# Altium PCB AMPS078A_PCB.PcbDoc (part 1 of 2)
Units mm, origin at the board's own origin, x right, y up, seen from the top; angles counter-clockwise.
Board outline 85 x 120 mm, 4 copper layers (Top Layer, Signal Layer 1, Signal Layer 2, Bottom Layer), stack 1.567 mm thick; 105 components, 52 nets, 354 pads, 440 vias.
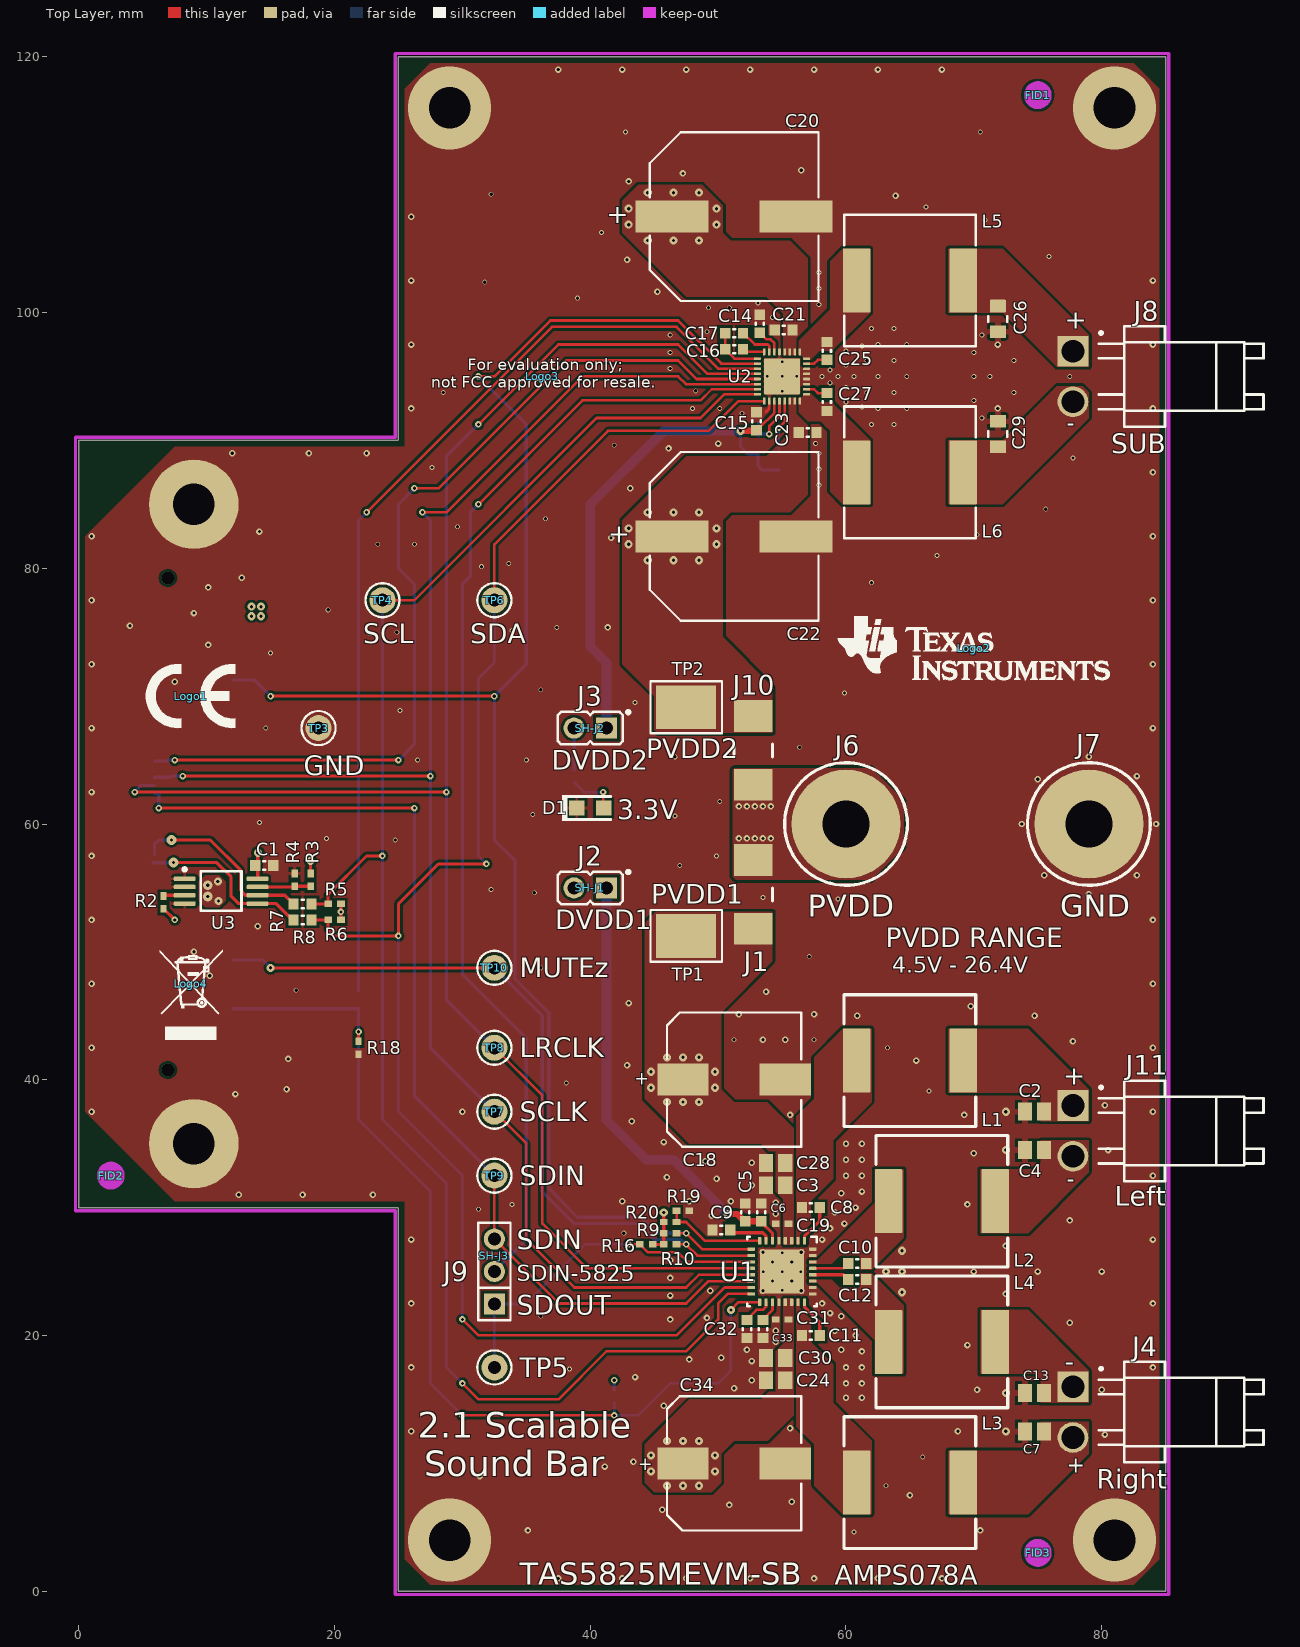
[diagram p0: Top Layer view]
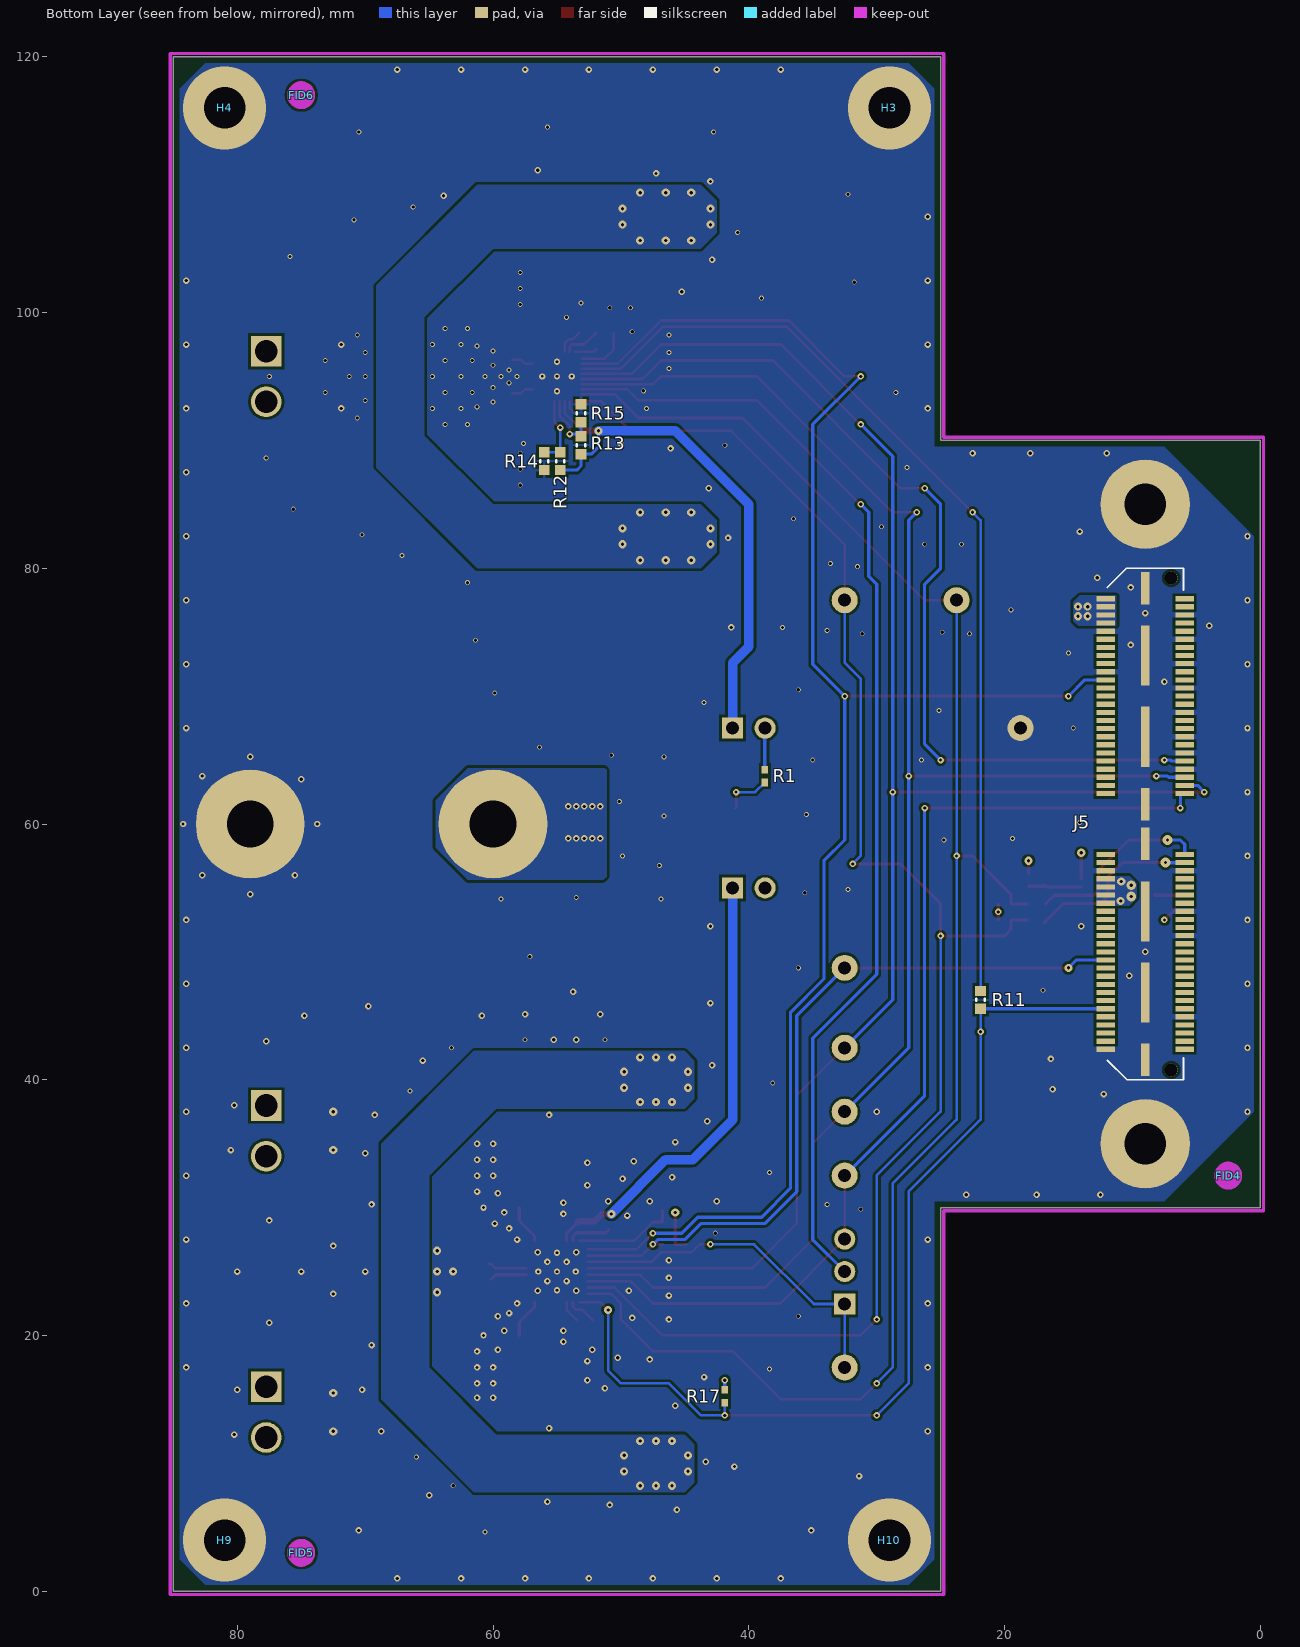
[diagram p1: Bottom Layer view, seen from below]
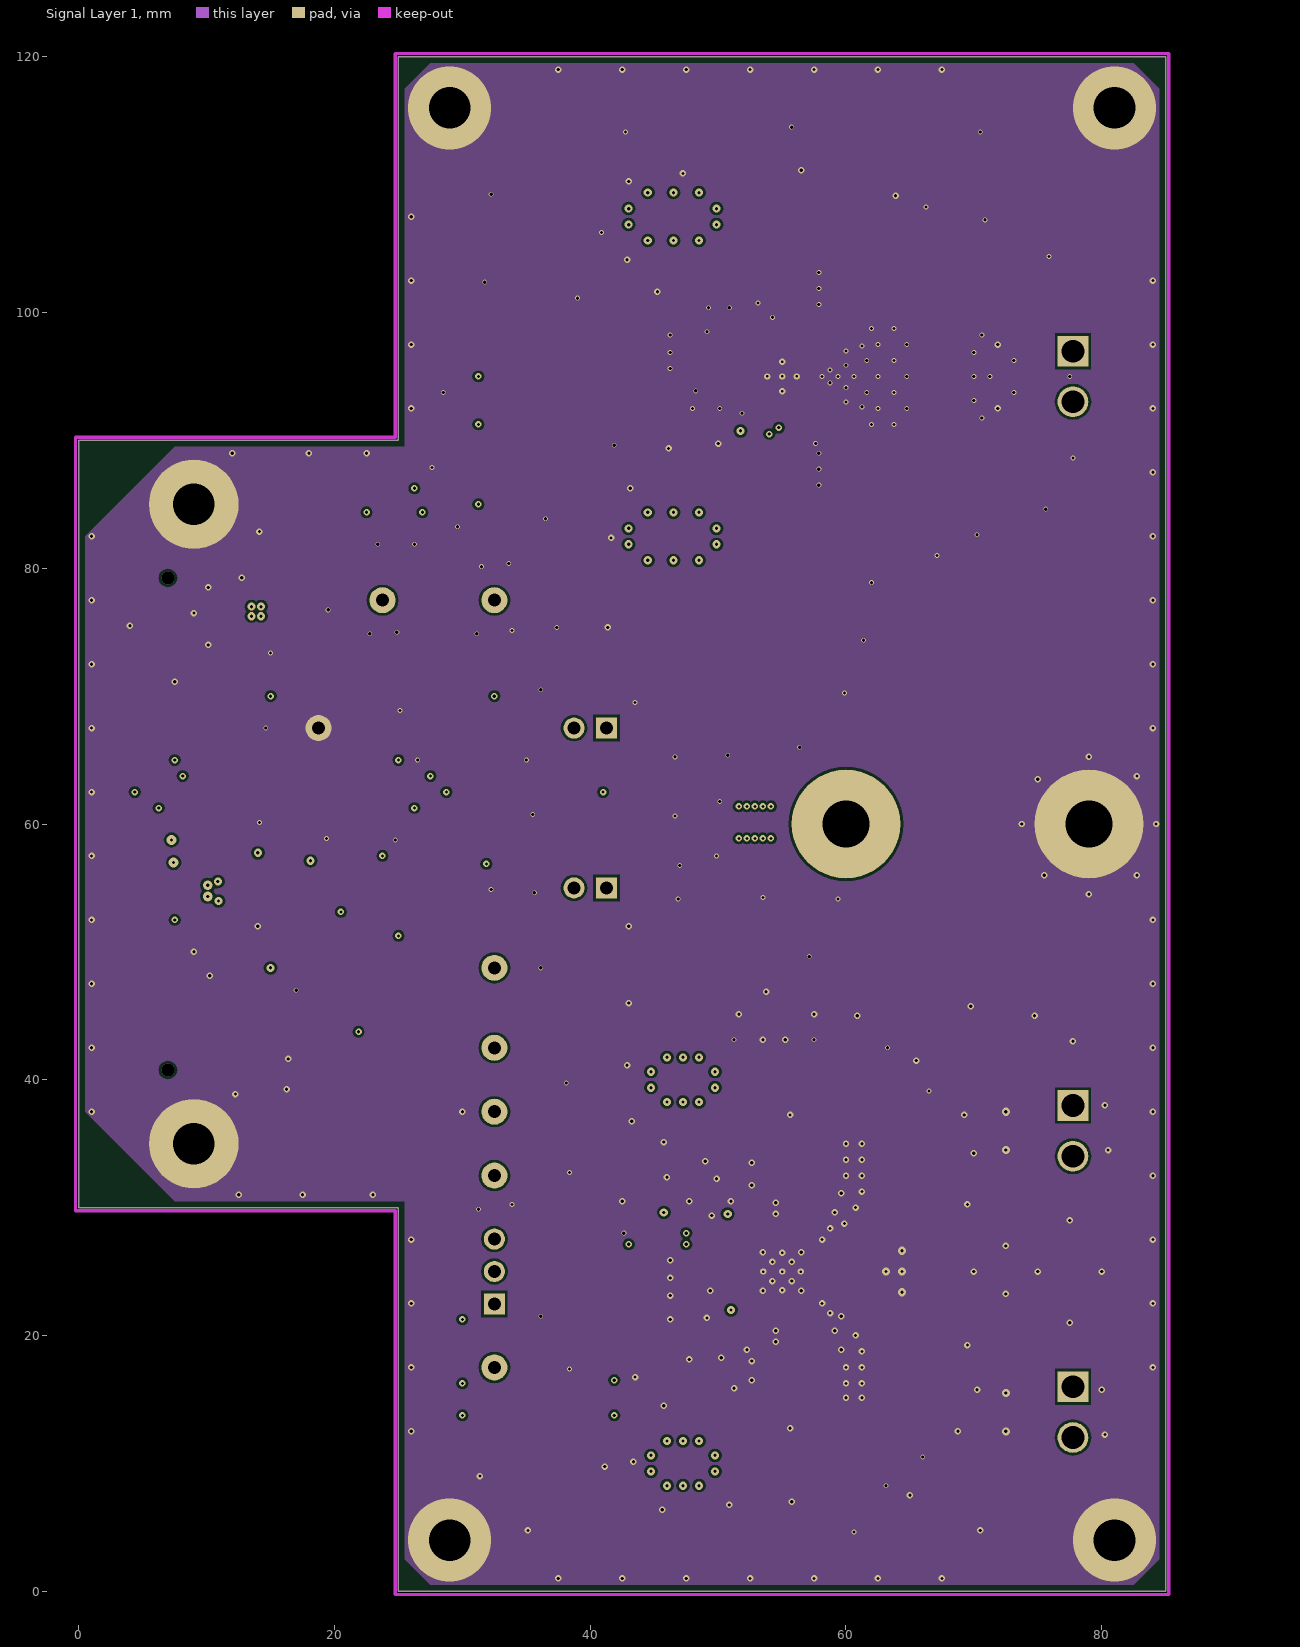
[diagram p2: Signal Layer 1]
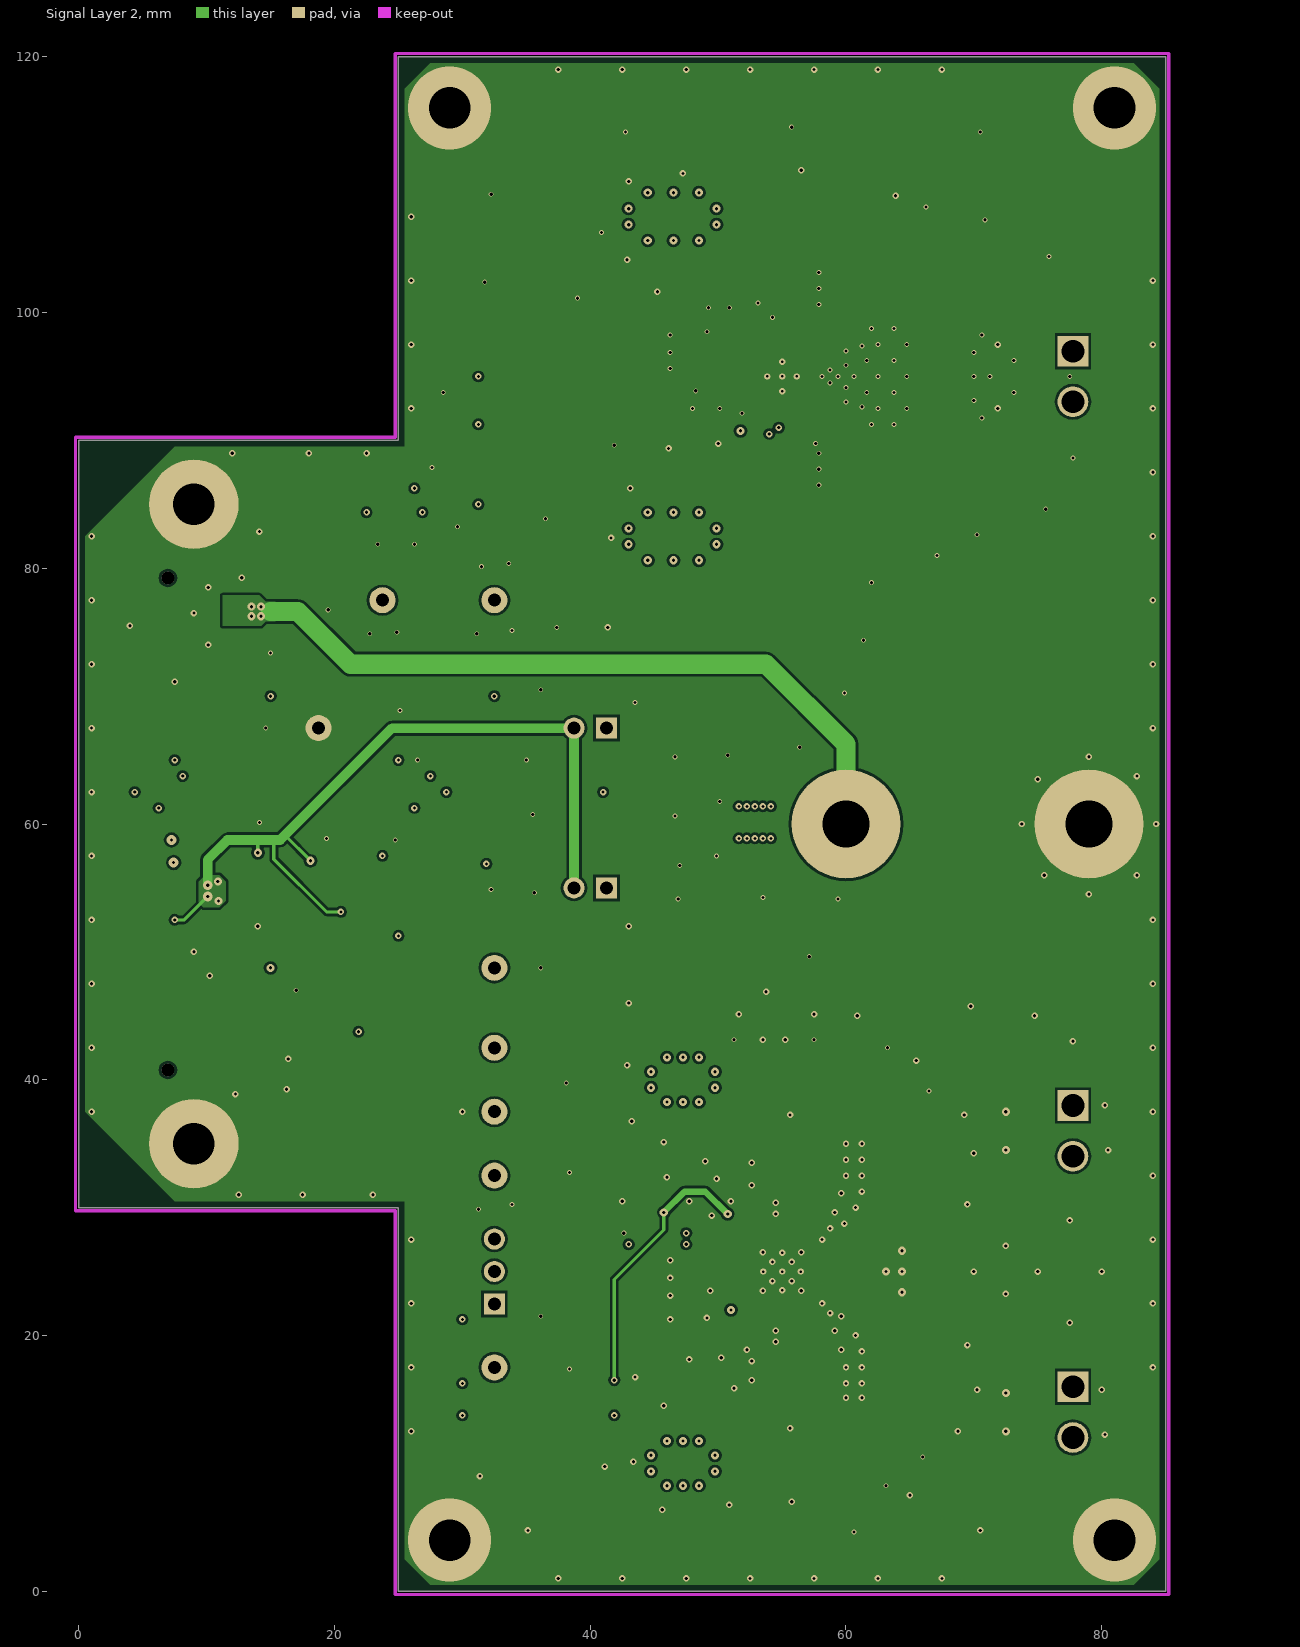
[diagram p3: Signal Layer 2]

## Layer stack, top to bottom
Top Solder: solder mask 0.0102, Solder Resist, Dk 3.5
Top Layer: signal copper 0.0696
Dielectric 1: prepreg 0.2032, FR-4, Dk 4.2
Signal Layer 1: signal copper 0.0356
Dielectric 2: core 0.9505, FR-4, Dk 4.2
Signal Layer 2: signal copper 0.0356
Dielectric 3: prepreg 0.2032, FR-4, Dk 4.2
Bottom Layer: signal copper 0.0696
Bottom Solder: solder mask 0.0102, Solder Resist, Dk 3.5

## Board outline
0,30 25,30 25,0 85,0 85,120 25,120 25,90 0,90

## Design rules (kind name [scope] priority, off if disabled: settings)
AcuteAngle [All] p1: minimum=4.50000000000000E+0001 checktracksonly=FALSE
AssemblyTestPointUsage [All] p1: valid=2
Clearance "Clearance Fiducial LibErrors" [InComponent('FID*')] p1: gap=0.2 ignorepadtopadclearanceinfootprint=TRUE except(0: Arc-SMDPad Arc-Hole Track-SMDPad Track-Hole SMDPad-Hole THPad-Hole Via-Hole Fill-Hole Poly-Hole Region-Hole Text-Hole)
Clearance Clearance_BoardEdge [OnCopper and Not InComponentClass('Logo') and not InComponentClass('FiducialMark') and not InRegion(1000,500,4000,800) and Not IsKeepout vs IsKeepOut] p2: gap=0.2 ignorepadtopadclearanceinfootprint=FALSE except(0: Arc-Hole Track-Hole SMDPad-Hole THPad-Hole Via-Hole Fill-Hole Poly-Hole Region-Hole Text-Hole)
Clearance Clearance_BoardEdge_Poly [OnCopper and InPoly vs IsKeepOut] p3: gap=0.2 ignorepadtopadclearanceinfootprint=FALSE except(0: Arc-Hole Track-Hole SMDPad-Hole THPad-Hole Via-Hole Fill-Hole Poly-Hole Region-Hole Text-Hole)
Clearance Clearance_BoardEdge_MountingHoles [OnCopper and InComponentClass('Mounting Hardware') vs IsKeepOut] p4: gap=0.2 ignorepadtopadclearanceinfootprint=FALSE except(0: Arc-Hole Track-Hole SMDPad-Hole THPad-Hole Via-Hole Fill-Hole Poly-Hole Region-Hole Text-Hole)
Clearance "Poly Clearance 3.3V" [InNamedPolygon('+3.3V_L04_P006')] p5: gap=0.2 ignorepadtopadclearanceinfootprint=FALSE except(0: Arc-Hole Track-Hole SMDPad-Hole THPad-Hole Via-Hole Fill-Hole Poly-Hole Region-Hole Text-Hole)
Clearance "Poly Clearance Outputs" [(InNet('SPK1_OUTA+') AND InNet('SPK1_OUTA-') AND InNet('SPK1_OUTB+') AND InNet('SPK1_OUTB-') AND InNet('SPK2_OUTA+') AND InNet('SPK2_OUTA-') AND InNet('SPK2_OUTB+') AND InNet('SPK2_OUTB-')) vs (InComponent('UD1') AND InComponent('UD2'))] p6: gap=0.2 ignorepadtopadclearanceinfootprint=FALSE except(0: Arc-Hole Track-Hole SMDPad-Hole THPad-Hole Via-Hole Fill-Hole Poly-Hole Region-Hole Text-Hole)
Clearance "Poly Clearance PVDD" [All] p7: gap=0.2 ignorepadtopadclearanceinfootprint=FALSE except(0: Arc-Hole Track-Hole SMDPad-Hole THPad-Hole Via-Hole Fill-Hole Poly-Hole Region-Hole Text-Hole)
Clearance Clearance_Keepouts [((IsTrack Or IsArc) And Not InPoly) And IsFree and IsKeepOut vs ((IsTrack Or IsArc) And Not InPoly) And IsFree and IsKeepOut] p8: gap=0 ignorepadtopadclearanceinfootprint=FALSE
Clearance Clearance_Poly [InPolygon] p9: gap=0.2 ignorepadtopadclearanceinfootprint=FALSE except(0: Arc-Hole Track-Hole SMDPad-Hole THPad-Hole Via-Hole Fill-Hole Poly-Hole Region-Hole Text-Hole)
Clearance [All] p10: gap=0.2 ignorepadtopadclearanceinfootprint=FALSE except(0: Arc-Hole Track-Hole SMDPad-Hole THPad-Hole Via-Hole Fill-Hole Poly-Hole Region-Hole Text-Hole)
ComponentClearance "TAS5754 Clearance" [InComponent('U2') vs InComponent('C*')] p1: gap=0.251 collisioncheckmode=3 verticalgap=0 showdistances=FALSE
ComponentClearance ComponentClearance_MountingHoles_FiducialMarks [InComponentClass('Mounting Holes') vs InComponentClass('FiducialMark')] p2: gap=1.27 collisioncheckmode=3 verticalgap=0.254 showdistances=FALSE
ComponentClearance ComponentClearance_Shunt [InComponentClass('Header') vs InComponentClass('Shunt')] p3: gap=0 collisioncheckmode=3 verticalgap=0 showdistances=FALSE
ComponentClearance ComponentClearance_Logo [InComponentClass('Logo')] p4: gap=0 collisioncheckmode=3 verticalgap=0 showdistances=FALSE
ComponentClearance ComponentClearance_ScrewToNut [(HasFootprint('NY PMS 440 0025 PH')) vs (HasFootprint('Keystone_1902C'))] p5: gap=0 collisioncheckmode=3 verticalgap=0 showdistances=FALSE
ComponentClearance ComponentClearance_MountingHoles [InComponentClass('Mounting Holes')] p6: gap=6.35 collisioncheckmode=3 verticalgap=2540 showdistances=FALSE
ComponentClearance ComponentClearance_SmallPassives [HasFootprint('0402*') or HasFootprint('0603*') or HasFootprint('0805*') or HasFootprint('CAP*') or HasFootprint('DEM*') or HasFootprint('IND*') or HasFootprint('RHB*') or HasFootprint('SM*') or HasFootprint('TSSOP*') vs HasFootprint('0402*') or HasFootprint('0603*') or HasFootprint('0805*') or HasFootprint('CAP*') or HasFootprint('DEM*') or HasFootprint('IND*') or HasFootprint('RHB*') or HasFootprint('SM*') or HasFootprint('TSSOP*')] p7: gap=0.2 collisioncheckmode=3 verticalgap=0 showdistances=FALSE
ComponentClearance ComponentClearance_THtoSMT [IsThruComponent vs IsSMTComponent] p8: gap=0 collisioncheckmode=3 verticalgap=0 showdistances=FALSE
ComponentClearance ComponentClearance_THtoTH [IsThruComponent vs IsThruComponent] p9: gap=0.25 collisioncheckmode=3 verticalgap=0 showdistances=FALSE
ComponentClearance [All] p10: gap=1.016 collisioncheckmode=3 verticalgap=0.254 showdistances=FALSE
DiffPairsRouting [All] p1: maxlimit=2.54 minlimit=0.254 mostfreqgap=0.254 toplayer_minwidth=0.381 toplayer_maxwidth=0.381 toplayer_prefwidth=0.381 midlayer1_minwidth=0.381 midlayer1_maxwidth=0.381 midlayer1_prefwidth=0.381 midlayer2_minwidth=0.381 midlayer2_maxwidth=0.381 midlayer2_prefwidth=0.381 bottomlayer_minwidth=0.381 bottomlayer_maxwidth=0.381 bottomlayer_prefwidth=0.381 maxuncoupledlength=25.4
FabricationTestPointUsage TestPointUsage [All] p1: valid=2 allowmultiple=FALSE
FabricationTestpoint Testpoint [All] p1: side=3 testpointundercomponent=TRUE minsize=1.016 maxsize=2.54 preferedsize=1.524 minholesize=0 maxholesize=1.016 preferedholesize=0.813 testpointgrid=0.025 allowsidetop=TRUE allowsidebottom=TRUE usegrid=TRUE gridtolerance=0
FanoutControl Fanout_LCC [IsLCC] p1: bgadir=Out bgaviamode=Centered fanoutstyle=Auto fanoutdirection=Alternating viagrid=0.025 // Fanout_LCC (Default Rule)
FanoutControl Fanout_BGA [IsBGA] p2: bgadir=Out bgaviamode=Centered fanoutstyle=Auto fanoutdirection=Alternating viagrid=0.025 // Fanout_BGA (Default Rule)
FanoutControl Fanout_Default [All] p4: bgadir=Out bgaviamode=Centered fanoutstyle=Auto fanoutdirection=Alternating viagrid=0.025 // Fanout_Default (Default Rule)
FanoutControl Fanout_Small [(CompPinCount < 5)] p5: bgadir=Out bgaviamode=Centered fanoutstyle=Auto fanoutdirection=OutThenIn viagrid=0.025 // Fanout_Small (Default Rule)
Height [All] p1: minheight=0 maxheight=40 prefheight=25
HoleSize [All] p1: absolutevalues=TRUE maxlimit=3.81 minlimit=0.191 maxpercent=80.000 minpercent=20.000
HoleToHoleClearance "Hole 2 Hole For Hardware" [(InComponentClass('Screw') OR InComponentClass('Standoff') OR InComponentClass('Washer')) vs (InComponentClass('Screw') OR InComponentClass('Standoff') OR InComponentClass('Washer'))] p1: gap=0 allowstackedmicrovias=TRUE
HoleToHoleClearance [All] p2: gap=0.254 allowstackedmicrovias=TRUE
MinimumAnnularRing MinimumAnnularRing_ThermalPadVias [IsVia and InAnyComponent] p1: minimumring=0.15
MinimumAnnularRing [All] p2: minimumring=0.064
MinimumSolderMaskSliver "MinSolderMaskSliver LibErrors" [HasFootprint('DB*') or HasFootprint('DC*') or HasFootprint('RSM*')] p1: minsoldermaskwidth=0.089
MinimumSolderMaskSliver MinimumSolderMaskSliver_Logo [InComponentClass('Logo') vs InComponentClass('Logo')] p2: minsoldermaskwidth=0.018
MinimumSolderMaskSliver [All] p3: minsoldermaskwidth=0.127
PlaneConnect [All] p1: planeconnectstyle=Relief reliefexpansion=0.254 reliefentries=4 reliefconductorwidth=0.254 reliefairgap=0.254
PolygonConnect "GND Full Flood" [InComponentClass('GND Full Flood') vs InNet('GND')] p1: connectstyle=Direct reliefconductorwidth=0.254 reliefentries=4 polygonreliefangle="90 Angle" airgapwidth=0.254
PolygonConnect "GND Thermals 0.75mm" [InComponentClass('GND Thermals 0.75mm') vs InNet('GND')] p2: connectstyle=Relief reliefconductorwidth=0.75 reliefentries=4 polygonreliefangle="90 Angle" airgapwidth=0.2
PolygonConnect "GND Thermals 0.5mm" [InComponentClass('GND Thermals 0.5mm') vs InNet('GND')] p3: connectstyle=Relief reliefconductorwidth=0.5 reliefentries=4 polygonreliefangle="90 Angle" airgapwidth=0.2
PolygonConnect "GND Thermals 0.25mm" [InComponentClass('GND Thermals 0.25mm') vs InNet('GND')] p4: connectstyle=Relief reliefconductorwidth=0.25 reliefentries=4 polygonreliefangle="90 Angle" airgapwidth=0.2
PolygonConnect PreFlood [All] p5: connectstyle=Direct reliefconductorwidth=0.254 reliefentries=4 polygonreliefangle="90 Angle" airgapwidth=0.254
RoutingVias ThermalPadVias [IsVia and InAnyComponent] p1: holewidth=0.2 width=0.5 viastyle="Through Hole" minholewidth=0.2 minwidth=0.381 maxholewidth=0.33 maxwidth=0.6
RoutingVias [All] p2: holewidth=0.203 width=0.711 viastyle="Through Hole" minholewidth=0.203 minwidth=0.381 maxholewidth=3.25 maxwidth=7
SilkToBoardRegionClearance [Not ((IsComment or IsDesignator) And (Hide <> 'False')) and not InRegion(1000,500,4000,800)] p1:
SilkToSilkClearance SilkToSilkClearance_Pb-FreeLogo [(HasFootprint('Pb-Free_Overlay_Medium') OR HasFootprint('Pb-Free_Overlay_Small')) vs (HasFootprint('Pb-Free_Overlay_Medium') OR HasFootprint('Pb-Free_Overlay_Small'))] p1: silktosilkclearance=0
SilkToSilkClearance [All] p2: silktosilkclearance=0.127
SilkToSolderMaskClearance "SilkToMask LibErrors" [HasFootprint('LTST*') or HasFootprint('DCU*')] p1: minsilkscreentomaskgap=0.076 clearancetoexposedcopper=FALSE
SilkToSolderMaskClearance SilkToComponentPadClearance [(IsPad or IsFill or IsRegion) and InAnycomponent] p2: minsilkscreentomaskgap=0.127 clearancetoexposedcopper=TRUE
SilkToSolderMaskClearance "Silk to Solder Mask Opening" [All] p3: minsilkscreentomaskgap=0.019 clearancetoexposedcopper=FALSE
SolderMaskExpansion [All] p1: expansion=0.05
Width [All] p1: maxlimit=5 minlimit=0.15 preferedwidth=0.25 checkconnectedcopper=TRUE
13 further rules are at their usual default settings.

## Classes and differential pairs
component class Shunt: SH-J1 SH-J2 SH-J3
component class "GND Thermals 0.25mm": D1 R4 R14 R15 U3
component class AssemblyNote: ZZ1 ZZ2 ZZ3
component class FiducialMark: FID1 FID2 FID3 FID4 FID5 FID6
component class AMPS078A_Hardware: FID1 FID2 FID3 FID4 FID5 FID6 H3 H4 H9 H10 Logo1 Logo2 Logo3 Logo4 SH-J1 SH-J2 SH-J3 ZZ1 ZZ2 ZZ3
component class Logo: Logo2
component class AMPS078A_TAS5825MRSM: C2 C3 C4 C5 C6 C7 C8 C9 C10 C11 C12 C13 C18 C19 C24 C28 C30 C31 C32 C33 C34 J4 J11 L1 L2 L3 L4 R9 R10 R16 R17 R19 R20 U1
component class AMPS078A_PPCMB-IO: C1 D1 J1 J2 J3 J5 J6 J7 J10 R1 R2 R3 R4 R5 R6 R7 R8 R18 R25 R26 R33 R35 R38 R39 R40 TP1 TP2 TP3 TP4 TP5 TP6 TP7 TP8 TP9 TP10 U3
component class Header: J2 J3 J9
component class "GND Full Flood": C18 C20 C22 C34 J5 J7 U1 U2
component class AMPS078A_TAS5720MRSM: C14 C15 C16 C17 C20 C21 C22 C23 C25 C26 C27 C29 J8 J9 L5 L6 R11 R12 R13 R14 R15 U2
component class "GND Thermals 0.5mm": C2 C4 C7 C13 C26 C29

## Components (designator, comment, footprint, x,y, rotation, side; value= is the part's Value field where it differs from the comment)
C1 "GRM188R71H104KA93D" 0603L 14.5,56.75 r0 top value=0.1uF
C2 "C0805C684K5RACTU" 0805L 74.75,37.5 r180 top value=0.68uF
C3 "C2012X5R1V156M125AC" 0805L 54.5,31.75 r0 top value=15uF
C4 "C0805C684K5RACTU" 0805L 74.75,34.5 r180 top value=0.68uF
C5 "C0603C475K8PACTU" 0603L 52.125,29.625 r270 top value=4.7uF
C6 "C0603C104K4RACTU" 0603L 53.375,29.625 r90 top value=0.1uF
C7 "C0805C684K5RACTU" 0805L 74.75,12.5 r180 top value=0.68uF
C8 "GCM188R71H224KA64D" 0603L 57.25,30 r180 top value=0.22uF
C9 "C0603C105K4PACTU" 0603L 50.25,28.25 r180 top value=1uF
C10 "GCM188R71H224KA64D" 0603L 60.875,25.625 r0 top value=0.22uF
C11 "GCM188R71H224KA64D" 0603L 57.25,20 r180 top value=0.22uF
C12 "GCM188R71H224KA64D" 0603L 60.875,24.375 r0 top value=0.22uF
C13 "C0805C684K5RACTU" 0805L 74.75,15.5 r180 top value=0.68uF
C14 "GRM188R71C105KA12D" 0603L 53.25,99.125 r90 top value=1uF
C15 "GRM188R71C105KA12D" 0603L 53,91.5 r90 top value=1uF
C16 "GRM188R71C105KA12D" 0603L 51.25,97.125 r0 top value=1uF
C17 "GRM188R71C105KA12D" 0603L 51.25,98.375 r0 top value=1uF
C18 "+" SM_RADIAL_10BMM 51.25,40 r0 top locked value=390uF
C19 "CGA2B3X7R1H104K050BB" 0402L 55,28.75 r180 top value=0.1uF
C20 "+" CAPSMT_62_KE0 51.25,107.5 r0 top locked value=470uF
C21 "GRM188R71H104KA93D" 0603L 55.125,98.625 r180 top value=0.1uF
C22 "+" CAPSMT_62_KE0 51.25,82.5 r0 top locked value=470uF
C23 "GRM188R71H104KA93D" 0603L 57,90.625 r0 top value=0.1uF
C24 "C2012X5R1V156M125AC" 0805L 54.5,16.5 r0 top value=15uF
C25 "GCM188R71H224KA64D" 0603L 58.5,97 r90 top value=0.22uF
C26 "C2012X7R1H684M125AB" 0805_HV1 71.875,99.5 r270 top value=0.68uF
C27 "GCM188R71H224KA64D" 0603L 58.5,93 r270 top value=0.22uF
C28 "C2012X5R1V156M125AC" 0805L 54.5,33.5 r0 top value=15uF
C29 "C2012X7R1H684M125AB" 0805_HV1 71.875,90.5 r90 top value=0.68uF
C30 "C2012X5R1V156M125AC" 0805L 54.5,18.25 r0 top value=15uF
C31 "CGA2B3X7R1H104K050BB" 0402L 55,21.25 r180 top value=0.1uF
C32 "C0603C105K4PACTU" 0603L 52.25,20.5 r270 top value=1uF
C33 "C0603C105K4PACTU" 0603L 53.5,20.5 r270 top value=1uF
C34 "+" SM_RADIAL_10BMM 51.25,10 r0 top locked value=390uF
D1 "3.3V" LTST-C170KGKT_Green 40,61.25 r180 top value=Green
FID1 "Fiducial" Fiducial6.4-20 75,117 r0 top
FID2 "Fiducial" Fiducial6.4-20 2.5,32.5 r0 top
FID3 "Fiducial" Fiducial6.4-20 75,3 r0 top
FID4 "Fiducial" Fiducial6.4-20 2.5,32.5 r180 bottom
FID5 "Fiducial" Fiducial6.4-20 75,3 r180 bottom
FID6 "Fiducial" Fiducial6.4-20 75,117 r180 bottom
H3 "Nut" Harwin_R30-1003002 29,116 r180 bottom
H4 "Nut" Harwin_R30-1003002 81,116 r180 bottom
H9 "Nut" Harwin_R30-1003002 81,4 r180 bottom
H10 "Nut" Harwin_R30-1003002 29,4 r180 bottom
J1 "PVDD1" HARWIN_S1911-46R 52.75,54.5 r270 top
J2 "DVDD1" Sullins_PBC02SAAN 40,55 r270 top
J3 "DVDD2" Sullins_PBC02SAAN 40,67.5 r270 top
J4 "Right" JST_B2PS-VH 77.75,14 r0 top locked
J5 "QTS-050-01-F-D-A" CONN_QTS-050-01-F-D-A 9,60 r270 bottom locked
J6 "PVDD" Keystone_7006 60,60 r0 top
J7 "GND" Keystone_7007 79,60 r0 top locked
J8 "SUB" JST_B2PS-VH 77.75,95 r0 top
J9 "SDIN_SEL" PBC03SAAN 32.5,25 r90 top
J10 "PVDD2" HARWIN_S1911-46R 52.75,65.75 r90 top
J11 "Left" JST_B2PS-VH 77.75,36 r0 top
L1 "1274AS-H-100M=P3" DEM10050C 65,41.5 r0 top locked value=10uH
L2 "1274AS-H-100M=P3" DEM10050C 67.5,30.5 r0 top locked value=10uH
L3 "1274AS-H-100M=P3" DEM10050C 65,8.5 r0 top value=10uH
L4 "1274AS-H-100M=P3" DEM10050C 67.5,19.5 r0 top value=10uH
L5 "1274AS-H-100M=P3" DEM10050C 65,102.5 r0 top locked value=10uH
L6 "1274AS-H-100M=P3" DEM10050C 65,87.5 r0 top locked value=10uH
Logo1 "CE Mark" CE_Mark_5mm 8.75,70 r0 top
Logo2 "Texas Instruments" TI_Stacked_Overlay_Small 70,73.75 r0 top
Logo3 "FCC disclaimer" FCC_disclaimer_stacked 36.25,95 r0 top
Logo4 "WEEE logo" WEEE_Minimum 8.75,47.5 r0 top
R1 "Resistor" 0402L 38.75,63.75 r90 bottom value=332
R2 "Resistor" 0402L 6.625,53.875 r270 top value=10.0k
R3 "Resistor" 0402L 18.125,55.625 r270 top value=10.0k
R4 "Resistor" 0402L 16.875,55.625 r270 top value=10.0k
R5 "Resistor" 0402L 20,53.75 r0 top value=2.20k
R6 "Resistor" 0402L 20,52.5 r0 top value=2.20k
R7 "Resistor" 0603L 17.5,53.75 r180 top value=0
R8 "Resistor" 0603L 17.5,52.5 r180 top value=0
R9 "RMCF0402FT10K0" 0402L 46.25,28 r180 top value=10.0k
R10 "RMCF0402FT10K0" 0402L 46.25,27.125 r180 top value=10.0k
R11 "CRCW06030000Z0EA" 0603L 21.875,46.25 r270 bottom value=0
R12 "DNP" 0603L 54.75,88.375 r270 bottom value=22.0k
R13 "DNP" 0603L 53.125,89.625 r270 bottom value=22.0k
R14 "CRCW06030000Z0EA" 0603L 56,88.375 r90 bottom value=0
R15 "CRCW06030000Z0EA" 0603L 53.125,92.125 r270 bottom value=0
R16 "RMCF0402FT10K0" 0402L 44.375,27.125 r0 top value=10.0k
R17 "RMCF0402FT10K0" 0402L 41.875,15.25 r90 bottom value=10.0k
R18 "ERJ-2RKF1003X" 0402L 21.875,42.5 r90 top value=100k
R19 "ERJ-2GE0R00X" 0402L 47.25,29.75 r0 top value=0
R20 "DNP" 0402L 46.25,28.875 r180 top value=0
SH-J1 "SNT-100-BK-G" SNT-100-BK-G 40,55 r0 top value=1x2
SH-J2 "SNT-100-BK-G" SNT-100-BK-G 40,67.5 r0 top value=1x2
SH-J3 "SNT-100-BK-G" SNT-100-BK-G 32.5,26.25 r90 top value=1x2
TP1 "PVDD1" Testpoint_Keystone_Compact 47.5,51.25 r0 top
TP2 "PVDD2" Testpoint_Keystone_Compact 47.5,69.125 r0 top
TP3 "GND" Keystone5001 18.75,67.5 r90 top
TP4 "SCL" Keystone5003 23.75,77.5 r90 top
TP5 "SDOUT" Keystone5003 32.5,17.5 r90 top
TP6 "SDA" Keystone5003 32.5,77.5 r90 top
TP7 "SCLK" Keystone5003 32.5,37.5 r90 top
TP8 "LRCLK" Keystone5003 32.5,42.5 r90 top
TP9 "SDIN" Keystone5003 32.5,32.5 r90 top
TP10 "MUTEz" Keystone5003 32.5,48.75 r90 top
U1 "TAS5825MRHBR" RHB0032N 55,25 r270 top locked
U2 "TAS5720MRSMR" RSM0032B 55,95 r0 top locked
U3 "EEPROM_8P" TSSOP-8 11.125,54.75 r0 top
ZZ1 "These assemblies must comply with workmanship standards IPC-A-610 Class 2, unless otherwise specified." AssemblyNote 3,129 r0 top
ZZ2 "These assemblies are ESD sensitive, ESD precautions shall be observed." AssemblyNote 3,126 r0 top
ZZ3 "These assemblies must be clean and free from flux and all contaminants. Use of no clean flux is not acceptable." AssemblyNote 3,123 r0 top

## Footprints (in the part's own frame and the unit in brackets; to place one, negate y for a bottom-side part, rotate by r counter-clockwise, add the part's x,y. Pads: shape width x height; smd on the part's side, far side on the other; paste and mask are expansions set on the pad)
0402L [mm] "0402 from SM-752 data"
  rect 0.6x0.5 smd: 1(-0.5,0) 2(0.5,0)
  body extent -0.55,-0.3 0.55,0.3, height 0.6
0603L [mm] "0603 from SM-752 data"
  rect 0.8x0.85 smd: 1(-0.7,0) 2(0.7,0)
  silkscreen extent -0.07,-0.33 0.07,0.33, body extent -0.87,-0.47 0.87,0.47, height 1
0805_HV1 [mm] "Custom footprint based on analyzing multiple manufacturer recommendations"
  rrect10% 1x1.25 smd: 1(-1,0) 2(1,0)
  silkscreen extent -0.2,-0.75 0.2,0.75, body extent -1.1,-0.72 1.1,0.73, height 1.45
0805L [mm] "0805 from SM-752 data"
  rect 1.1x1.4 smd: 1(-0.75,0) 2(0.75,0)
  body extent -1.1,-0.72 1.1,0.72, height 1.45
AssemblyNote [mm] "Assembly Note"
CAPSMT_62_KE0 [mm] "12.5 x 13.5mm:  Chemi-Con KE0"
  rect 5.7x2.5 smd: 1(-4.85,0) 2(4.85,0)
  silkscreen extent -6.6,-6.6 6.6,6.6, body extent -6.6,-6.6 6.6,6.6, height 14
CE_Mark_5mm [mm] "Minimum text height for CE Mark"
  silkscreen extent -3.5,-2.5 3.5,2.5
CONN_QTS-050-01-F-D-A [mil] "SAMTEC"
  rect 16x57 smd: 1(-693.75,121.5) 2(-693.75,-121.5) 3(-668.75,121.5) 4(-668.75,-121.5) 5(-643.75,121.5) 6(-643.75,-121.5) 7(-618.75,121.5) 8(-618.75,-121.5) 9(-593.75,121.5) 10(-593.75,-121.5) 11(-568.75,121.5) 12(-568.75,-121.5) 13(-543.75,121.5) 14(-543.75,-121.5) 15(-518.75,121.5) 16(-518.75,-121.5) 17(-493.75,121.5) 18(-493.75,-121.5) 19(-468.75,121.5) 20(-468.75,-121.5) 21(-443.75,121.5) 22(-443.75,-121.5) 23(-418.75,121.5) 24(-418.75,-121.5) 25(-393.75,121.5) 26(-393.75,-121.5) 27(-368.75,121.5) 28(-368.75,-121.5) 29(-343.75,121.5) 30(-343.75,-121.5) 31(-318.75,121.5) 32(-318.75,-121.5) 33(-293.75,121.5) 34(-293.75,-121.5) 35(-268.75,121.5) 36(-268.75,-121.5) 37(-243.75,121.5) 38(-243.75,-121.5) 39(-218.75,121.5) 40(-218.75,-121.5) 41(-193.75,121.5) 42(-193.75,-121.5) 43(-168.75,121.5) 44(-168.75,-121.5) 45(-143.75,121.5) 46(-143.75,-121.5) 47(-118.75,121.5) 48(-118.75,-121.5) 49(-93.75,121.5) 50(-93.75,-121.5) 51(93.75,121.5) 52(93.75,-121.5) 53(118.75,121.5) 54(118.75,-121.5) 55(143.75,121.5) 56(143.75,-121.5) 57(168.75,121.5) 58(168.75,-121.5) 59(193.75,121.5) 60(193.75,-121.5) 61(218.75,121.5) 62(218.75,-121.5) 63(243.75,121.5) 64(243.75,-121.5) 65(268.75,121.5) 66(268.75,-121.5) 67(293.75,121.5) 68(293.75,-121.5) 69(318.75,121.5) 70(318.75,-121.5) 71(343.75,121.5) 72(343.75,-121.5) 73(368.75,121.5) 74(368.75,-121.5) 75(393.75,121.5) 76(393.75,-121.5) 77(418.75,121.5) 78(418.75,-121.5) 79(443.75,121.5) 80(443.75,-121.5) 81(468.75,121.5) 82(468.75,-121.5) 83(493.75,121.5) 84(493.75,-121.5) 85(518.75,121.5) 86(518.75,-121.5) 87(543.75,121.5) 88(543.75,-121.5) 89(568.75,121.5) 90(568.75,-121.5) 91(593.75,121.5) 92(593.75,-121.5) 93(618.75,121.5) 94(618.75,-121.5) 95(643.75,121.5) 96(643.75,-121.5) 97(668.75,121.5) 98(668.75,-121.5) 99(693.75,121.5) 100(693.75,-121.5)
  rect 100x25 smd: 101(-726,0) 104(-61.25,0) 105(61.25,0) 108(726.25,0)
  rect 185x25 smd: 102(-518.75,0) 103(-268.75,0) 106(269,0) 107(518.75,0)
  round 39 hole 40 unplated: MH1(-757.5,80) MH2(757.5,80)
  silkscreen extent -788,-117 787,118, body extent -787,-140 788,140, height 166
DEM10050C [mm] "MuRata inductor"
  rrect5% 2.15x5 smd: 1(-4.175,0) 2(4.175,0)
  body extent -5.15,-5.15 5.15,5.15, height 5
FCC_disclaimer_stacked [mm]
Fiducial6.4-20 [mm]
  round 0.635 smd mask+0.683: 1(0,0)
  Top Layer keep-out circle w1.178: c0,0 r0.5
Harwin_R30-1003002 [mm] "Standoff Hex Brass M3"
  body extent -3,-3.46 3,3.46, height 30.02
HARWIN_S1911-46R [mm] "HARWIN"
  rect 2.48x3 smd mask+0.102: 1(-2.69,0) 2(2.69,0)
  silkscreen extent -0.5,-1.5 0.5,1.5, body extent -3.42,-1.25 3.43,1.26, height 0.99
JST_B2PS-VH [mm] "JST Sales America Inc"
  rect 2.4x2.4 hole 1.778: 1(0,1.98)
  round 2.4 hole 1.778: 2(0,-1.98)
  silkscreen extent 2,-3.93 14.9,3.93, body extent -0.57,-3.93 14.9,3.93, height 8.52
Keystone5001 [mil] "For Keystone 500x miniature loop terminals"
  round 80 hole 40: 1(0,0)
  silkscreen extent -52,-52 52,52, body extent -49,-49 49,49, height 182
Keystone5003 [mil] "For Keystone 500x miniature loop terminals"
  round 80 hole 40: 1(0,0)
  silkscreen extent -52,-52 52,52, body extent -49,-49 49,49, height 182
Keystone_7006 [mm] "KEYSTONE"
  round 8.5 hole 3.658: 1(0,0)
  silkscreen extent -4.8,-4.8 4.8,4.8, body extent -5.68,-5.69 5.7,5.69, height 26.47
Keystone_7007 [mm] "KEYSTONE"
  round 8.5 hole 3.658: 1(0,0)
  silkscreen extent -4.8,-4.8 4.8,4.8, body extent -5.71,-5.66 5.67,5.72, height 26.48
LTST-C170KGKT_Green [mm] "LITE-ON"
  rect 1.2x1.2 smd: 1(-1.05,0) 2(1.05,0)
  silkscreen extent -1.6,-1 2.2,1, body extent -1.05,-0.67 1.05,0.67, height 1.1
PBC03SAAN [mm] "Sullins 100mil, 1x3, 230 mil above insulator"
  rect 1.65x1.65 hole 1.016: 1(-2.54,0)
  round 1.65 hole 1.016: 2(0,0) 3(2.54,0)
  silkscreen extent -3.81,-1.27 3.81,1.27, body extent -3.81,-1.27 3.81,1.27, height 8.38
RHB0032N [mm] "QFN, 32-Leads, Body 5x5mm, Pitch 0.5mm, Thermal Pad 3.45x3.45mm"
  rrect40% 0.6x0.25 smd: 1(-2.4,1.75) 2(-2.4,1.25) 3(-2.4,0.75) 4(-2.4,0.25) 5(-2.4,-0.25) 6(-2.4,-0.75) 7(-2.4,-1.25) 8(-2.4,-1.75) 17(2.4,-1.75) 18(2.4,-1.25) 19(2.4,-0.75) 20(2.4,-0.25) 21(2.4,0.25) 22(2.4,0.75) 23(2.4,1.25) 24(2.4,1.75)
  rrect40% 0.25x0.6 smd: 9(-1.75,-2.4) 10(-1.25,-2.4) 11(-0.75,-2.4) 12(-0.25,-2.4) 13(0.25,-2.4) 14(0.75,-2.4) 15(1.25,-2.4) 16(1.75,-2.4) 25(1.75,2.4) 26(1.25,2.4) 27(0.75,2.4) 28(0.25,2.4) 29(-0.25,2.4) 30(-0.75,2.4) 31(-1.25,2.4) 32(-1.75,2.4)
  rrect3% 3.45x3.45 smd paste-1.725: 33(0,0)
  rrect7% 1.49x1.49 on Top Paste: ""(-0.845,0.845) ""(-0.845,-0.845) ""(0.845,0.845) ""(0.845,-0.845)
  silkscreen extent -2.72,-2.73 2.72,2.73, body extent -2.5,-2.5 2.5,2.5, height 0.9
RSM0032B [mm] "QFN, 32-Leads, Body 4x4mm, Pitch 0.4mm, Thermal Pad 2.8x2.8mm, TI Recommended"
  rrect50% 0.55x0.2 smd: 1(-1.925,1.4) 2(-1.925,1) 3(-1.925,0.6) 4(-1.925,0.2) 5(-1.925,-0.2) 6(-1.925,-0.6) 7(-1.925,-1) 8(-1.925,-1.4) 17(1.925,-1.4) 18(1.925,-1) 19(1.925,-0.6) 20(1.925,-0.2) 21(1.925,0.2) 22(1.925,0.6) 23(1.925,1) 24(1.925,1.4)
  rrect50% 0.2x0.55 smd: 9(-1.4,-1.925) 10(-1,-1.925) 11(-0.6,-1.925) 12(-0.2,-1.925) 13(0.2,-1.925) 14(0.6,-1.925) 15(1,-1.925) 16(1.4,-1.925) 25(1.4,1.925) 26(1,1.925) 27(0.6,1.925) 28(0.2,1.925) 29(-0.2,1.925) 30(-0.6,1.925) 31(-1,1.925) 32(-1.4,1.925)
  rrect8% 1.23x1.23 on Top Paste: 33(-0.715,-0.715) 33(-0.715,0.715) 33(0.715,-0.715) 33(0.715,0.715)
  rrect4% 2.8x2.8 smd paste-1.4: 33(0,0)
  body extent -2,-2 2,2, height 1.01
SM_RADIAL_10BMM [mm] "Nichicon 10x10"
  rect 4x2.5 smd: 1(-4,0) 2(4,0)
  silkscreen extent -5.25,-5.25 5.25,5.25, body extent -5.25,-5.25 5.25,5.25, height 10.5
SNT-100-BK-G [mil] "Samtec STEP model"
  round 1 on Mech3: 0(0,0)
  body extent -100,-50 100,50, height 344
Sullins_PBC02SAAN [mm] "Sullins 100mil, 1x2, 230 mil above insulator"
  rect 1.65x1.65 hole 1.016: 1(0,1.27)
  round 1.65 hole 1.016: 2(0,-1.27)
  silkscreen extent -1.37,-2.54 1.27,3.1, body extent -1.27,-2.54 1.27,2.54, height 8.38
Testpoint_Keystone_Compact [mil] "Compact SMT test point"
  rect 185x135 smd: 1(0,0)
  silkscreen extent -110,-80 110,80, body extent -75,-56 75,56, height 91
TI_Stacked_Overlay_Small [mm]
  silkscreen extent -10.63,-2.49 10.63,2.49
TSSOP-8 [mm] "TSSOP, 8-Leads, Body 3.1x4.5mm (max), Pitch 0.65mm, IPC Medium Density"
  rrect50% 1.7x0.35 smd: 1(-2.85,0.975) 2(-2.85,0.325) 3(-2.85,-0.325) 4(-2.85,-0.975) 5(2.85,-0.975) 6(2.85,-0.325) 7(2.85,0.325) 8(2.85,0.975)
  silkscreen extent -2.97,-1.55 1.6,1.82, body extent -3.2,-1.55 3.2,1.55, height 1.07
WEEE_Minimum [mm] "WEEElie bin"
  silkscreen extent -2.42,-4.38 2.52,2.65

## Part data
C1 C21 C23: library part CMP-0007434-4, "CAP, CERM, 0.1 uF, 50 V, +/- 10%, X7R, 0603", Cap_Case=0603, Manufacturer=MuRata, Supplier Part Number 1=490-1519-1-ND, TempCo=X7R, Tolerance_%=10%, Value1=Unknown, Value2=50V, ValueDisplayed=0.1uF
C2 C4 C7 C13: library part CMP-0007814-2, "CAP, CERM, 0.68 uF, 50 V, +/- 10%, X7R, 0805", Cap_Case=0805, Manufacturer=Kemet, NewPartNumber=CGA4J3X7R1H684M125AB, Supplier Part Number 1=399-8114-6-ND, TempCo=X7R, Tolerance_%=10%, Value1=Unknown, Value2=50V, ValueDisplayed=0.68uF
C3 C24 C28 C30: library part CMP-0007843-2, "CAP, CERM, 15 uF, 35 V, +/- 20%, X5R, 0805", Cap_Case=0805, Manufacturer=TDK, Supplier Part Number 1=445-14423-1-ND, TempCo=X5R, Tolerance_%=20%, Value1="0.001669 ohm", Value2=35V, ValueDisplayed=15uF
C5: library part CMP-0006949-5, "CAP, CERM, 4.7 uF, 10 V, +/- 10%, X5R, 0603", Cap_Case=0603, Manufacturer=Kemet, Supplier Part Number 1=399-5503-1-ND, TempCo=X5R, Tolerance_%=10%, Value1="0.006 ohm", Value2=10V, ValueDisplayed=4.7uF
C6: library part CMP-0006860-5, "CAP, CERM, 0.1 uF, 16 V, +/- 10%, X7R, 0603", Cap_Case=0603, Manufacturer=Kemet, Supplier Part Number 1=399-1096-1-ND, TempCo=X7R, Tolerance_%=10%, Value1=Unknown, Value2=16V, ValueDisplayed=0.1uF
C8 C10 C11 C12 C25 C27: library part CMP-0007145-4, "CAP, CERM, 0.22 uF, 50 V, +/- 10%, X7R, AEC-Q200 Grade 1, 0603", Cap_Case=0603, Manufacturer=MuRata, Supplier Part Number 1=490-5402-1-ND, TempCo=X7R, Tolerance_%=10%, Value1=Unknown, Value2=50V, ValueDisplayed=0.22uF
C9 C32 C33: library part CMP-0006868-5, "CAP, CERM, 1 uF, 16 V, +/- 10%, X5R, 0603", Cap_Case=0603, Manufacturer=Kemet, Supplier Part Number 1=399-5090-1-ND, TempCo=X5R, Tolerance_%=10%, Value1=Unknown, Value2=16V, ValueDisplayed=1uF
C14 C15 C16 C17: library part CMP-0007379-4, "CAP, CERM, 1 uF, 16 V, +/- 10%, X7R, 0603", Cap_Case=0603, Manufacturer=MuRata, Supplier Part Number 1=490-3900-1-ND, TempCo=X7R, Tolerance_%=10%, Value1="0.011 ohm", Value2=16V, ValueDisplayed=1uF
C18 C34: library part CMP-0011092-1, "CAP, AL, 390 uF, 35 V, +/- 20%, 0.08 ohm, SMD", Cap_Case=10x10, Manufacturer=Nichicon, PartNumber=UCL1V391MNL1GS, Supplier Part Number 1=493-3960-1-ND, Tolerance_%=20%, Value1="0.08 ohm", Value2=35V, ValueDisplayed=390uF
C19 C31: library part CMP-0006325-2, "CAP, CERM, 0.1 uF, 50 V, +/- 10%, X7R, AEC-Q200 Grade 1, 0402", Cap_Case=0402, Manufacturer=TDK, Supplier Part Number 1=445-6899-1-ND, TempCo=X7R, Tolerance_%=10%, Value1="0.039064 ohm", Value2=50V, ValueDisplayed=0.1uF
C20 C22: library part CMP-0010879-1, "CAP, AL, 470 uF, 35 V, +/- 20%, SMD", Cap_Case=KE0, Manufacturer=Chemi-Con, NewPartNumber=EMVE350ARA471MKE0S, PartNumber=EMVE350ATR471MKE0S, Tolerance_%=20%, Value1=Unknown, Value2=35V, ValueDisplayed=470uF
C26 C29: library part CMP-0007882-2, "CAP, CERM, 0.68 uF, 50 V, +/- 20%, X7R, 0805", Cap_Case=0805, Manufacturer=TDK, NewPartNumber=CGA4J3X7R1H684M125AB, Supplier Part Number 1=445-7546-1-ND, TempCo=X7R, Tolerance_%=20%, Value1=Unknown, Value2=50V, ValueDisplayed=0.68uF
D1: library part CMP-0002888-1, "LED, Green, SMD", Color=Green, Manufacturer=Lite-On, PartNumber=LTST-C170KGKT, Supplier Part Number 1=160-1414-1-ND, Value1=W, Value2=2V
FID1 FID2 FID3 FID4 FID5 FID6: library part CMP-0077181-1, "Fiducial mark.  There is nothing to buy or mount.", Manufacturer=N/A
H3 H4 H9 H10: library part CMP-0003674-1, "Standoff, HexBrass M3, 30 mm", Manufacturer=Harwin, PartNumber=R30-1003002, Supplier Part Number 1=R30-1003002-ND
J1 J10: library part CMP-0075020-1, "JUMPER TIN SMD", Manufacturer=Harwin, PartNumber=S1911-46R, Supplier Part Number 1=952-1740-1-ND
J2 J3: library part CMP-0054566-1, "Header, 100mil, 2x1, Gold, TH", Color=Black, Current_A=3A, Manufacturer="Sullins Connector Solutions", PartNumber=PBC02SAAN, Supplier Part Number 1=S1011E-02-ND, Voltage_V=1.8kV
J4 J8 J11: library part CMP-0074989-1, "Header (friction lock), 3.96mm, 2x1, Tin, R/A, TH", Manufacturer="JST Manufacturing", PartNumber=B2PS-VH(LF)(SN), Supplier Part Number 1=455-1648-ND
J5: library part CMP-0055971-1, "Connector, 100 Pos. 0.635mm, SMT", Manufacturer=Samtec, Supplier Part Number 1=QTS-050-01-F-D-A-ND
J6: library part CMP-0055127-1, "Binding Post, RED, TH", Manufacturer=Keystone, PartNumber=7006, Supplier Part Number 1=36-7006-ND
J7: library part CMP-0055128-1, "Binding Post, BLACK, TH", Manufacturer=Keystone, PartNumber=7007, Supplier Part Number 1=36-7007-ND
J9: library part CMP-0002334-1, "Header, 100mil, 3x1, Gold, TH", Manufacturer="Sullins Connector Solutions", PartNumber=PBC03SAAN, Supplier Part Number 1=S1011E-03-ND
L1 L2 L3 L4 L5 L6: library part CMP-0077807-1, "Inductor, Shielded, Ferrite, 10 µH, 4.4 A, 0.0304 ohm, SMD", Manufacturer=MuRata, PartNumber=1274AS-H-100M{}P3, Supplier Part Number 1=490-10850-1-ND, Value1="0.0304 ohm", Value2=4.4A, ValueDisplayed=10µH
Logo1: library part CMP-0074844-1
Logo2: library part CMP-0074838-1, "Texas Instrument Corporate Signature"
Logo3: library part CMP-0074847-1, "FCC_disclaimer"
Logo4: library part CMP-0074769-1
R1: library part CMP-0026297-2, "RES, 332, 1%, 0.063 W, AEC-Q200 Grade 0, 0402", Manufacturer=Vishay-Dale, PartNumber=CRCW0402332RFKED, Power_W=63mW, Supplier Part Number 1=541-332LCT-ND, TempCo="100 ppm/C", Tolerance_%=1%, Value2=0.063W, Value_Code=332R, ValueDisplayed=332
R2 R3 R4: library part CMP-0025958-3, "RES, 10.0 k, 1%, 0.063 W, AEC-Q200 Grade 0, 0402", Manufacturer=Vishay-Dale, PartNumber=CRCW040210K0FKED, Power_W=63mW, Supplier Part Number 1=541-10.0KLCT-ND, TempCo="100 ppm/C", Tolerance_%=1%, Value2=0.063W, Value_Code=10k0, ValueDisplayed=10.0k
R5 R6: library part CMP-0026231-2, "RES, 2.20 k, 1%, 0.063 W, AEC-Q200 Grade 0, 0402", Manufacturer=Vishay-Dale, PartNumber=CRCW04022K20FKED, Power_W=63mW, Supplier Part Number 1=541-2.20KLCT-ND, TempCo="100 ppm/C", Tolerance_%=1%, Value2=0.063W, Value_Code=2k20, ValueDisplayed=2.20k
R7 R8: library part CMP-0025697-4, "RES, 0, 5%, 0.1 W, AEC-Q200 Grade 0, 0603", Manufacturer=Vishay-Dale, PartNumber=CRCW06030000Z0EA, Power_W=100mW, Supplier Part Number 1=541-0.0GCT-ND, TempCo="200 ppm/C", Tolerance_%=5%, Value2=0.1W, Value_Code=0000, ValueDisplayed=0
R9 R10 R16 R17: library part CMP-0026754-1, "RES, 10.0 k, 1%, 0.063 W, AEC-Q200 Grade 0, 0402", Manufacturer="Stackpole Electronics Inc", Power_W=63mW, Supplier Part Number 1=RMCF0402FT10K0CT-ND, TempCo="100 ppm/C", Tolerance_%=1%, Value2=0.063W, Value_Code=10k0, ValueDisplayed=10.0k
R11 R14 R15: library part CMP-0025697-4, "RES, 0, 5%, 0.1 W, AEC-Q200 Grade 0, 0603", Manufacturer=Vishay-Dale, Power_W=100mW, Supplier Part Number 1=541-0.0GCT-ND, TempCo="200 ppm/C", Tolerance_%=5%, Value2=0.1W, Value_Code=0000, ValueDisplayed=0
R12 R13: library part CMP-0022692-3, "RES, 22.0 k, 1%, 0.1 W, AEC-Q200 Grade 0, 0603", Manufacturer=Panasonic, PartNumber=ERJ-3EKF2202V, Power_W=100mW, Supplier Part Number 1=P22.0KHCT-ND, TempCo="100 ppm/C", Tolerance_%=1%, Value2=0.1W, Value_Code=22k0, ValueDisplayed=22.0k
R18: library part CMP-0026659-1, "RES, 100 k, 1%, 0.1 W, 0402", Manufacturer=Panasonic, Power_W=100mW, TempCo="100 ppm/C", Tolerance_%=1%, Value2=0.1W, Value_Code=100k
R19: library part CMP-0026992-3, "RES, 0, 5%, 0.1 W, AEC-Q200 Grade 0, 0402", Manufacturer=Panasonic, Power_W=100mW, Supplier Part Number 1=P0.0JCT-ND, TempCo="600 ppm/C", Tolerance_%=5%, Value2=0.1W, Value_Code=0000, ValueDisplayed=0
R20: library part CMP-0026992-3, "RES, 0, 5%, 0.1 W, AEC-Q200 Grade 0, 0402", Manufacturer=Panasonic, PartNumber=ERJ-2GE0R00X, Power_W=100mW, Supplier Part Number 1=P0.0JCT-ND, TempCo="600 ppm/C", Tolerance_%=5%, Value2=0.1W, Value_Code=0000, ValueDisplayed=0
SH-J1 SH-J2 SH-J3: library part CMP-0003623-3, "Shunt, 100mil, Gold plated, Black", Alternate Manufacturer=3M, Alternate PartNumber=969102-0000-DA, Manufacturer=Samtec, Supplier Part Number 1=SAM8858-ND
TP1 TP2: library part CMP-0055153-1, "Test Point, Compact, SMT", Manufacturer=Keystone, PartNumber=5016, Supplier Part Number 1=36-5016TR-ND
TP3: library part CMP-0055138-1, "Test Point, Miniature, Black, TH", Color=Black, Manufacturer=Keystone, PartNumber=5001, Supplier Part Number 1=36-5001-ND
TP4 TP5 TP6 TP7 TP8 TP9 TP10: library part CMP-0055140-1, "Test Point, Miniature, Orange, TH", Color=Orange, Manufacturer=Keystone, PartNumber=5003, Supplier Part Number 1=36-5003-ND
U1: library part CMP-0077820-2, "4.5 V to 26.4 V, Inductor-Less, Digital Input, Stereo, Closed-Loop Class-D Audio Amplifier with 96-kHz/192-kHz Extended Audio Processing, RHB0032N (VQFN-32)", Alternate Manufacturer="Texas Instruments", Alternate PartNumber=TAS5825MRHBT
U2: library part CMP-0075842-2, "Closed Loop I2S Input Amplifier with Power Limiter, PVDDmax of 26.4V, RSM0032B (VQFN-32)", Alternate Manufacturer="Texas Instruments", Alternate PartNumber=TAS5720MRSMT
U3: library part CMP-0005242-2, "EEPROM, 512KBIT, 400KHZ, 8TSSOP", Manufacturer=Microchip, PartNumber=24LC512-I/ST, Supplier Part Number 1=24LC512-I/ST-ND
ZZ1: library part CMP-0077238-1
ZZ2: library part CMP-0077236-1
ZZ3: library part CMP-0077237-1

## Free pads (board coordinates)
  round 7 hole 3.25: 0(9,35) 0(9,85)

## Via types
v1: diameter 0.508, hole 0.254, Top Layer to Bottom Layer, tented both sides, 228 vias
v2: diameter 0.381, hole 0.254, Top Layer to Bottom Layer, tented both sides, 125 vias
v3: diameter 0.635, hole 0.254, Top Layer to Bottom Layer, tented both sides, 61 vias
v4: diameter 0.5, hole 0.2, Top Layer to Bottom Layer, 10 vias
v5: diameter 0.508, hole 0.254, Top Layer to Bottom Layer, 8 vias
v6: diameter 6.5, hole 3.25, Top Layer to Bottom Layer, tented both sides, 4 vias
v7: diameter 0.762, hole 0.254, Top Layer to Bottom Layer, tented both sides, 4 vias

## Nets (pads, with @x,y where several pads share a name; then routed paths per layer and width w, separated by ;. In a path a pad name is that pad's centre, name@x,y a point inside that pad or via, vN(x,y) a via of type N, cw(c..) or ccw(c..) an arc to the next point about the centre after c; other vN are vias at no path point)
3.3V: C1.1 J2.2 J3.2 J5.58 J5.60 J5.62 J5.64 R1.2 R2.2 R3.1 R5.2 R6.2 U3.8 | length 71.8
  Top Layer w0.25: R2.2@6.625,53.375 v1(7.5,52.5) ; U3.8@13.975,55.725 14,55.75 14,56.75 v3(14,57.75) ; R3.1@18.125,56.125 v3(18.125,57.125) ; R6.2@20.5,52.5 v1(20.5,53.125) R5.2@20.5,53.75
  Signal Layer 2 w0.25: v1(7.5,52.5) 8.25,52.5 10.086,54.336 v7(10.086,54.339) ; v3(14,57.75) 14,58.75 ; 15.25,58.75 15.25,57.25 19.375,53.125 v1(20.5,53.125) ; 16.125,59.125 v3(18.125,57.125)
  Signal Layer 2 w0.75: v7(10.086,55.214) 10.086,57.211 11.625,58.75 14,58.75 15.25,58.75 15.75,58.75 16.125,59.125 24.5,67.5 J3.2@38.73,67.5 J2.2@38.73,55
  Bottom Layer w0.25: J3.2@38.73,67.5 38.75,67.48 R1.2@38.75,64.25
  other v3: 10.922,53.974 10.875,55.5
\MUTE: J5.78 R10.1 TP10.1 U1.10 | length 58.9
  Top Layer w0.2: R10.1@46.75,27.125 v1(47.5,27.125) 48.375,26.25 U1.10@52.6,26.25
  Top Layer w0.25: v3(15,48.75) TP10.1@32.5,48.75
  Bottom Layer w0.25: J5.78@12.086,49.364 14.386,49.364 v3(15,48.75) ; TP10.1@32.5,48.75 36.25,45 36.25,31.25 38.75,28.75 43.75,28.75 45,27.5 47.125,27.5 v1(47.5,27.125)
\PDN: J5.90 R11.2 R17.1 R18.2 U1.17 | length 76.4
  Top Layer w0.2: R18.2@21.875,43 v1(21.875,43.75) ; v1(30,13.75) v1(41.875,13.75) ; v3(51,22) 51.6,22.6 U1.17@53.25,22.6
  Bottom Layer w0.2: R11.2@21.875,45.55 v1(21.875,43.75) 21.875,36.875 27.5,31.25 27.5,16.25 v1(30,13.75) ; R17.1@41.875,14.75 v1(41.875,13.75) 43.75,13.75 46.25,16.25 50,16.25 51,17.25 v3(51,22)
  Bottom Layer w0.25: J5.90@12.086,45.554 21.871,45.554 R11.2@21.875,45.55
\SD: R11.1 U2.3 | length 75.6
  Top Layer w0.2: v1(22.5,84.375) 37,98.875 46.75,98.875 50.025,95.6 U2.3@53.075,95.6
  Bottom Layer w0.2: R11.1@21.875,46.95 21.875,83.75 v1(22.5,84.375)
\SPK_FAULT: J5.22 R9.1 U1.9 U2.2 | length 132.4
  Top Layer w0.2: v1(31.25,95) 32.5,95 36.875,99.375 46.875,99.375 50.25,96 U2.2@53.075,96 ; R9.1@46.75,28 v1(47.5,28) 48.75,26.75 U1.9@52.6,26.75
  Top Layer w0.25: v1(15,70) v1(32.5,70)
  Bottom Layer w0.25: J5.22@12.086,71.271 13.729,71.271 v1(15,70) ; v1(31.25,95) 35,91.25 35,72.5 v1(32.5,70) 32.5,58.75 34.125,57.125 34.125,47.875 36.75,45.25 36.75,31.5 39,29.25 44,29.25 45.25,28 v1(47.5,28)
ADR0: R12.1 R14.2 U2.13 | length 5.4
  Top Layer w0.2: v1(54.75,91) 55.2,91.45 U2.13@55.2,93.075
  Bottom Layer w0.2: v1(54.75,91) R12.1@54.75,89.075 R14.2@56,89.075
ADR1: R13.1 R15.2 U2.12 | length 5
  Top Layer w0.2: v1(54,90.5) 54,91.125 54.8,91.925 U2.12@54.8,93.075
  Bottom Layer w0.2: R15.2@53.125,91.425 R13.1@53.125,90.325 53.3,90.5 v1(54,90.5)
ADR2: R19.1 R20.1 U1.8 | length 8
  Top Layer w0.2: R19.1@46.75,29.75 R20.1@46.75,28.875 47.5,28.875 48.975,27.4 U1.8@53.25,27.4
BST_A+: C8.1 U1.1 | length 3.1
  Top Layer w0.25: U1.1@56.75,27.4 56.75,27.75 57.95,28.95 C8.1@57.95,30
BST_A-: C10.1 U1.29 | length 3
  Top Layer w0.2: U1.29@57.4,25.25 59.8,25.25 C10.1@60.175,25.625 ; C10.1@60.237,25.562 C10.1@60.3,25.625
BST_B+: C11.1 U1.24 | length 3.1
  Top Layer w0.25: U1.24@56.75,22.6 56.75,22.25 57.95,21.05 C11.1@57.95,20
BST_B-: C12.1 U1.28 | length 2.9
  Top Layer w0.25: U1.28@57.4,24.75 59.8,24.75 C12.1@60.175,24.375
BST_N: C27.1 U2.18 | length 1.7
  Top Layer w0.2: U2.18@56.925,94 57.5,94 57.8,93.7 C27.1@58.5,93.7
BST_P: C25.1 U2.23 | length 1.7
  Top Layer w0.2: U2.23@56.925,96 57.5,96 57.8,96.3 C25.1@58.5,96.3
DVDD1: C5.2 C6.1 J2.1 R9.2 R10.2 R16.2 R17.2 R20.2 U1.6 | length 60.6
  Top Layer w0.25: R16.2@44.875,27.125 R10.2@45.75,27.125 R9.2@45.75,28 R20.2@45.75,28.875 v3(45.75,29.625) ; C6.1@53.375,28.865 54.25,27.99 U1.6@54.25,27.4
  Top Layer w0.5: v3(50.75,29.5) 51.489,29.5 52.064,28.925 C5.2@52.125,28.925 53.315,28.925 C6.1@53.375,28.865
  Signal Layer 2 w0.25: v1(41.875,16.5) 41.875,24.375 45.75,28.25 v3(45.75,29.625)
  Signal Layer 2 w0.5: v3(45.75,29.625) 47.375,31.25 49,31.25 v3(50.75,29.5)
  Bottom Layer w0.25: R17.2@41.875,15.75 v1(41.875,16.5)
  Bottom Layer w0.75: J2.1@41.27,55 41.27,36.855 44.375,33.75 46.5,33.75 v3(50.75,29.5)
